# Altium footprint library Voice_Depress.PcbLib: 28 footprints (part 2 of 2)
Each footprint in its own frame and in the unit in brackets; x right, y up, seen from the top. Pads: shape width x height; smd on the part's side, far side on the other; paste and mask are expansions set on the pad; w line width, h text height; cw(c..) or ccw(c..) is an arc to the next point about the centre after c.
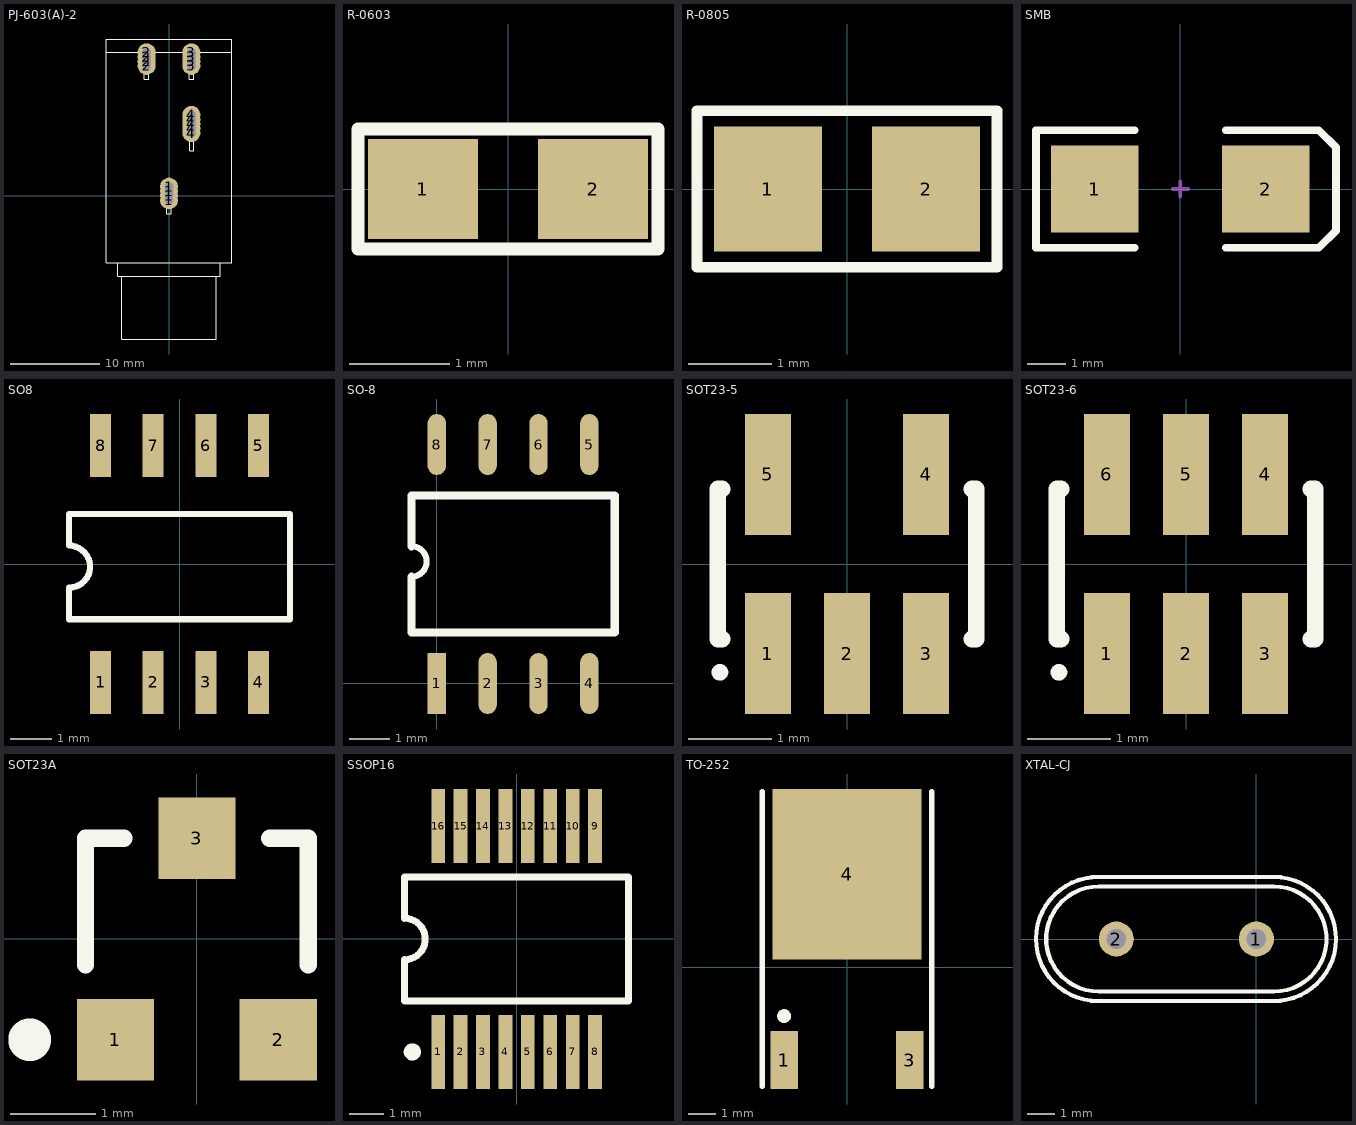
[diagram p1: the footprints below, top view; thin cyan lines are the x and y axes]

## PJ-603(A)-2 [mm] "会议话筒音频座"
height 10.4
pads (17):
  round 2 hole 1: 1(0,-0.508) 1(0,0) 1(0,0.508) 1(0,1.016) 2(-2.5,14.492) 2(-2.5,15) 2(-2.5,15.508) 2(-2.5,16.016) 3(2.5,14.492) 3(2.5,15) 3(2.5,15.508) 3(2.5,16.016) 4(2.5,7) 4(2.5,7.508) 4(2.5,8.016) 4(2.5,8.524) 4(2.5,9.032)
Top Overlay:
  lines w0.127: -7,16 7,16 ; -5.75,-7.5 -5.75,-9 5.75,-9 5.75,-7.5 ; -5.25,-9 -5.25,-14.5 -5.25,-16 5.25,-16 5.25,-14.5 5.25,-9 ; 7,-7.5 7,17.5 -7,17.5 -7,-7.5 7,-7.5 ; -2.75,13 -2.25,13 -2.25,15 -2.75,15 -2.75,13 ; -2.75,14 -2.25,14 -2.25,16 -2.75,16 -2.75,14 ; -0.25,-2 -0.25,0 0.25,0 0.25,-2 -0.25,-2 ; 2.25,13 2.75,13 2.75,15 2.25,15 2.25,13 ; 2.25,14 2.75,14 2.75,16 2.25,16 2.25,14 ; 2.29,5 2.79,5 2.79,7 2.29,7 2.29,5

## R-0603 [mm]
height 0.5
pads (2):
  rect 1.1x1 smd: 1(-0.85,0) 2(0.85,0)
Top Overlay:
  lines w0.127: -1.5,-0.6 1.5,-0.6 1.5,0.6 -1.5,0.6 -1.5,-0.6
3D body: height 0.45, standoff 0, extent -0.8,-0.419 0.8,0.381

## R-0805 [mm]
pads (2):
  rect 1.3x1.5 smd: 1(-0.95,0) 2(0.95,0)
Top Overlay:
  lines w0.127: -1.803,-0.94 -1.803,0.94 1.803,0.94 1.803,-0.94 -1.803,-0.94
3D body: height 0.55, standoff 0, extent -0.991,-0.61 1.009,0.65

## SMB [mm] "DO-214-AA/SMB; 2 C-Bend Leads; Body 5.3 x 3.6 mm, inc. leads (LxW)"
height 2.54
pads (2):
  rect 2.3x2.3 smd: 1(-2.25,0) 2(2.25,0)
Top Overlay:
  lines w0.2: -1.2,-1.55 -3.8,-1.55 -3.8,1.55 -1.2,1.55 ; 1.2,-1.55 3.65,-1.55 4.1,-1.1 4.1,1.1 3.65,1.55 1.2,1.55
Mechanical 1:
  lines w0.1: -0.2,0 0.2,0 ; 0,-0.2 0,0.2
3D body: height 2.5, standoff 0, extent -2.724,-1.981 2.876,1.919

## SO8 [mil]
height 452.76
pads (8):
  rect 20x60 smd: 1(-75,-112.5) 2(-25,-112.5) 3(25,-112.5) 4(75,-112.5) 5(75,112.5) 6(25,112.5) 7(-25,112.5) 8(-75,112.5)
Top Overlay:
  lines w6: -105,-52.5 75,-52.5 105,-52.5 105,47.5 75,47.5 -105,47.5 -105,17.5 cw(c-105,-2.5) -105,-22.5 -105,-52.5
3D body: height 66.93, standoff 0, extent -96,-117.11 96.91,119.11

## SO-8 [mil]
height 400
pads (8):
  rect 18x60 smd: 1(0.25,0)
  oval 18x60 smd: 2(50.25,0) 3(100.25,0) 4(150.25,0) 5(150.25,235) 6(100.25,235) 7(50.25,235) 8(0.25,235)
Top Overlay:
  lines w6: -24.75,105 ccw(c-24.75,120) -9.75,120 ccw(c-24.75,120) -24.75,135
  lines w8: -24.75,105 -24.75,50 175.25,50 175.25,185 -24.75,185 -24.75,135
3D body: height 66.93, standoff 0, extent -21,-5.11 171.91,231.11

## SOT23-5 [mm]
height 1.45
pads (5):
  rect 0.55x1.45 smd: 1(-0.95,-1.075) 2(0,-1.075) 3(0.95,-1.075) 4(0.95,1.075) 5(-0.95,1.075)
Top Overlay:
  circle w0.1: c-1.525,-1.3 r0.05
  lines w0.2: -1.5,-0.9 -1.55,-0.9 -1.55,0.9 -1.5,0.9 ; 1.5,-0.9 1.55,-0.9 1.55,0.9 1.5,0.9
3D body: height 1.2, standoff 0, extent -1.45,-1.397 1.45,1.403

## SOT23-6 [mm] "SOT-23/SC-74A; 5 Leads; Body 3.1 x 3 mm, inc. leads (LxW max)"
height 1.45
pads (6):
  rect 0.55x1.45 smd: 1(-0.95,-1.075) 2(0,-1.075) 3(0.95,-1.075) 4(0.95,1.075) 5(0,1.075) 6(-0.95,1.075)
Top Overlay:
  circle w0.1: c-1.525,-1.3 r0.05
  lines w0.2: -1.5,-0.9 -1.55,-0.9 -1.55,0.9 -1.5,0.9 ; 1.5,-0.9 1.55,-0.9 1.55,0.9 1.5,0.9
3D body: height 1.08, standoff -0.01, extent -1.397,-1.245 1.397,1.181

## SOT23A [mm] "SOT-23; 3 Leads; Body 3.0 x 2.5 mm, inc. leads (LxW max)"
height 1.2
pads (3):
  rect 0.9x0.95 smd: 1(-0.95,-1.175) 2(0.95,-1.175) 3(0,1.175)
Top Overlay:
  circle w0.25: c-1.95,-1.175 r0.125
  lines w0.2: -1.3,-0.3 -1.3,1.175 -0.85,1.175 ; 0.85,1.175 1.3,1.175 1.3,-0.3
3D body: height 1.2, standoff 0, extent -1.45,-1.422 1.45,1.378

## SSOP16 [mm] "SSOP; 16 Leads; Body Width 5.3 mm; Pitch 0.65 mm"
height 2
pads (16):
  rect 0.4x2.15 smd: 1(-2.275,-3.275) 2(-1.625,-3.275) 3(-0.975,-3.275) 4(-0.325,-3.275) 5(0.325,-3.275) 6(0.975,-3.275) 7(1.625,-3.275) 8(2.275,-3.275) 9(2.275,3.275) 10(1.625,3.275) 11(0.975,3.275) 12(0.325,3.275) 13(-0.325,3.275) 14(-0.975,3.275) 15(-1.625,3.275) 16(-2.275,3.275)
Top Overlay:
  circle w0.25: c-3.025,-3.275 r0.125
  lines w0.2: -3.25,-0.6 ccw(c-3.25,0) -3.25,0.6
  lines w0.203: -3.25,-0.6 -3.25,-1.8 3.25,-1.8 3.25,1.8 -3.25,1.8 -3.25,0.6
3D body: height 1.2, standoff 0, extent -2.485,-3.279 2.515,3.177

## TO-252 [mm] "D-PAK/TO-252-AA; 3 Leads (1 Cropped); Body 10.1 (inc. leads) x 6.6 mm (LxW max)"
height 2.4
pads (3):
  rect 1x2.1 smd: 1(-2.285,-3.375) 3(2.285,-3.375)
  rect 5.4x6.2 smd: 4(0,3.375)
Top Overlay:
  circle w0.25: c-2.285,-1.775 r0.125
  lines w0.2: -3.085,-4.325 -3.085,6.375 ; 3.085,-4.325 3.085,6.375
3D body: height 2.39, standoff -0.02, extent -3.27,-3.96 3.27,5.978

## XTAL-CJ [mil]
pads (2):
  round 50 hole 28: 1(0,0) 2(-200,0)
Top Overlay:
  lines w6: -226,-88.58 cw(c-226,0) -225.09,88.58 25,88.58 cw(c25,0) 24.07,-88.58 -226,-88.58 ; -225,-75 cw(c-225,0) -225,75 25,75 cw(c25,0) 25,-75 -225,-75
3D body: height 137.8, standoff -118.11, extent -326.36,-92 126.36,91.07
